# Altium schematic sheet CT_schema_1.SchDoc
size 488 x 436 mm
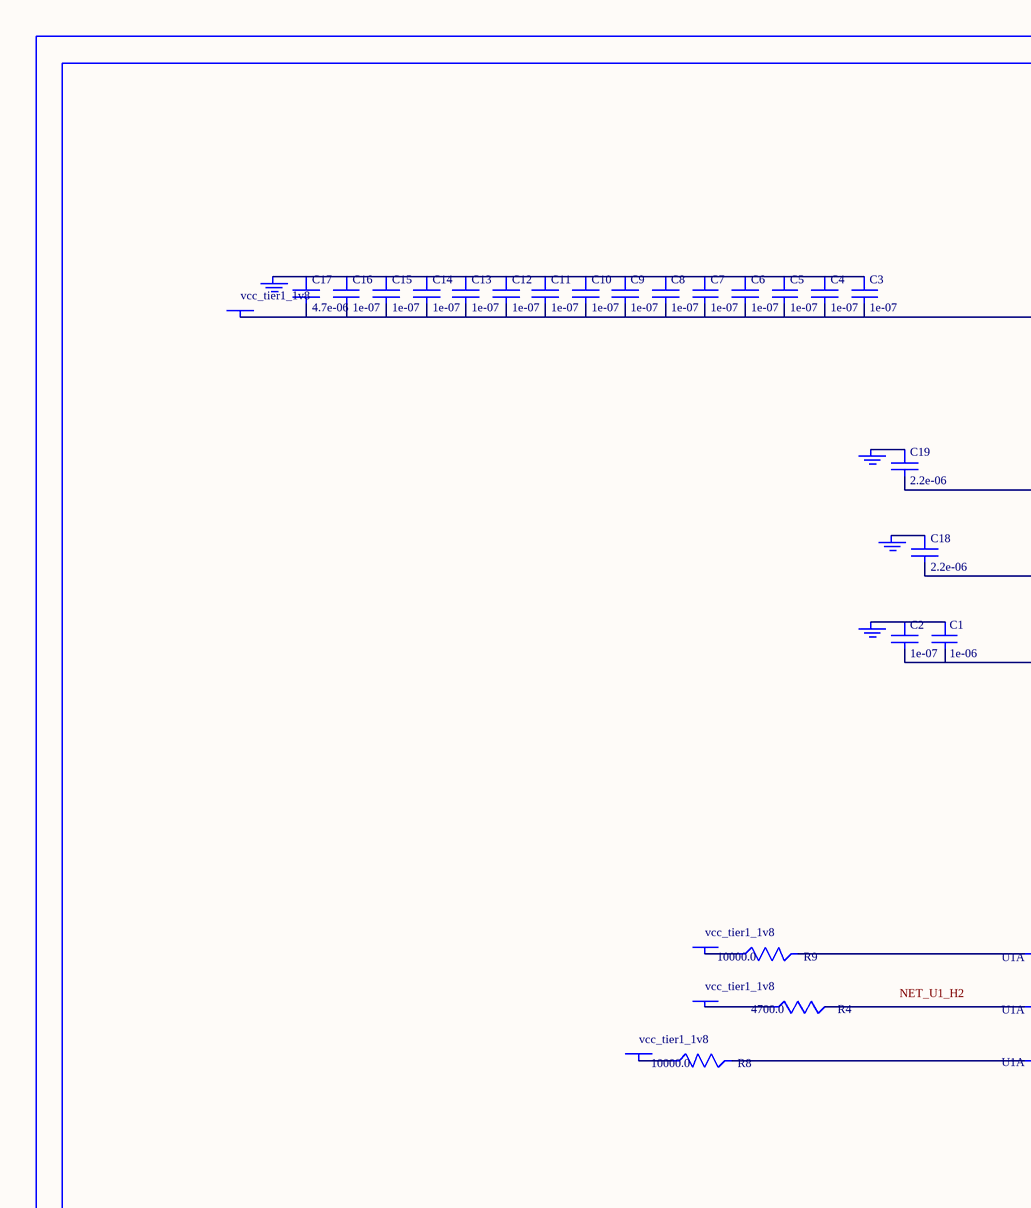
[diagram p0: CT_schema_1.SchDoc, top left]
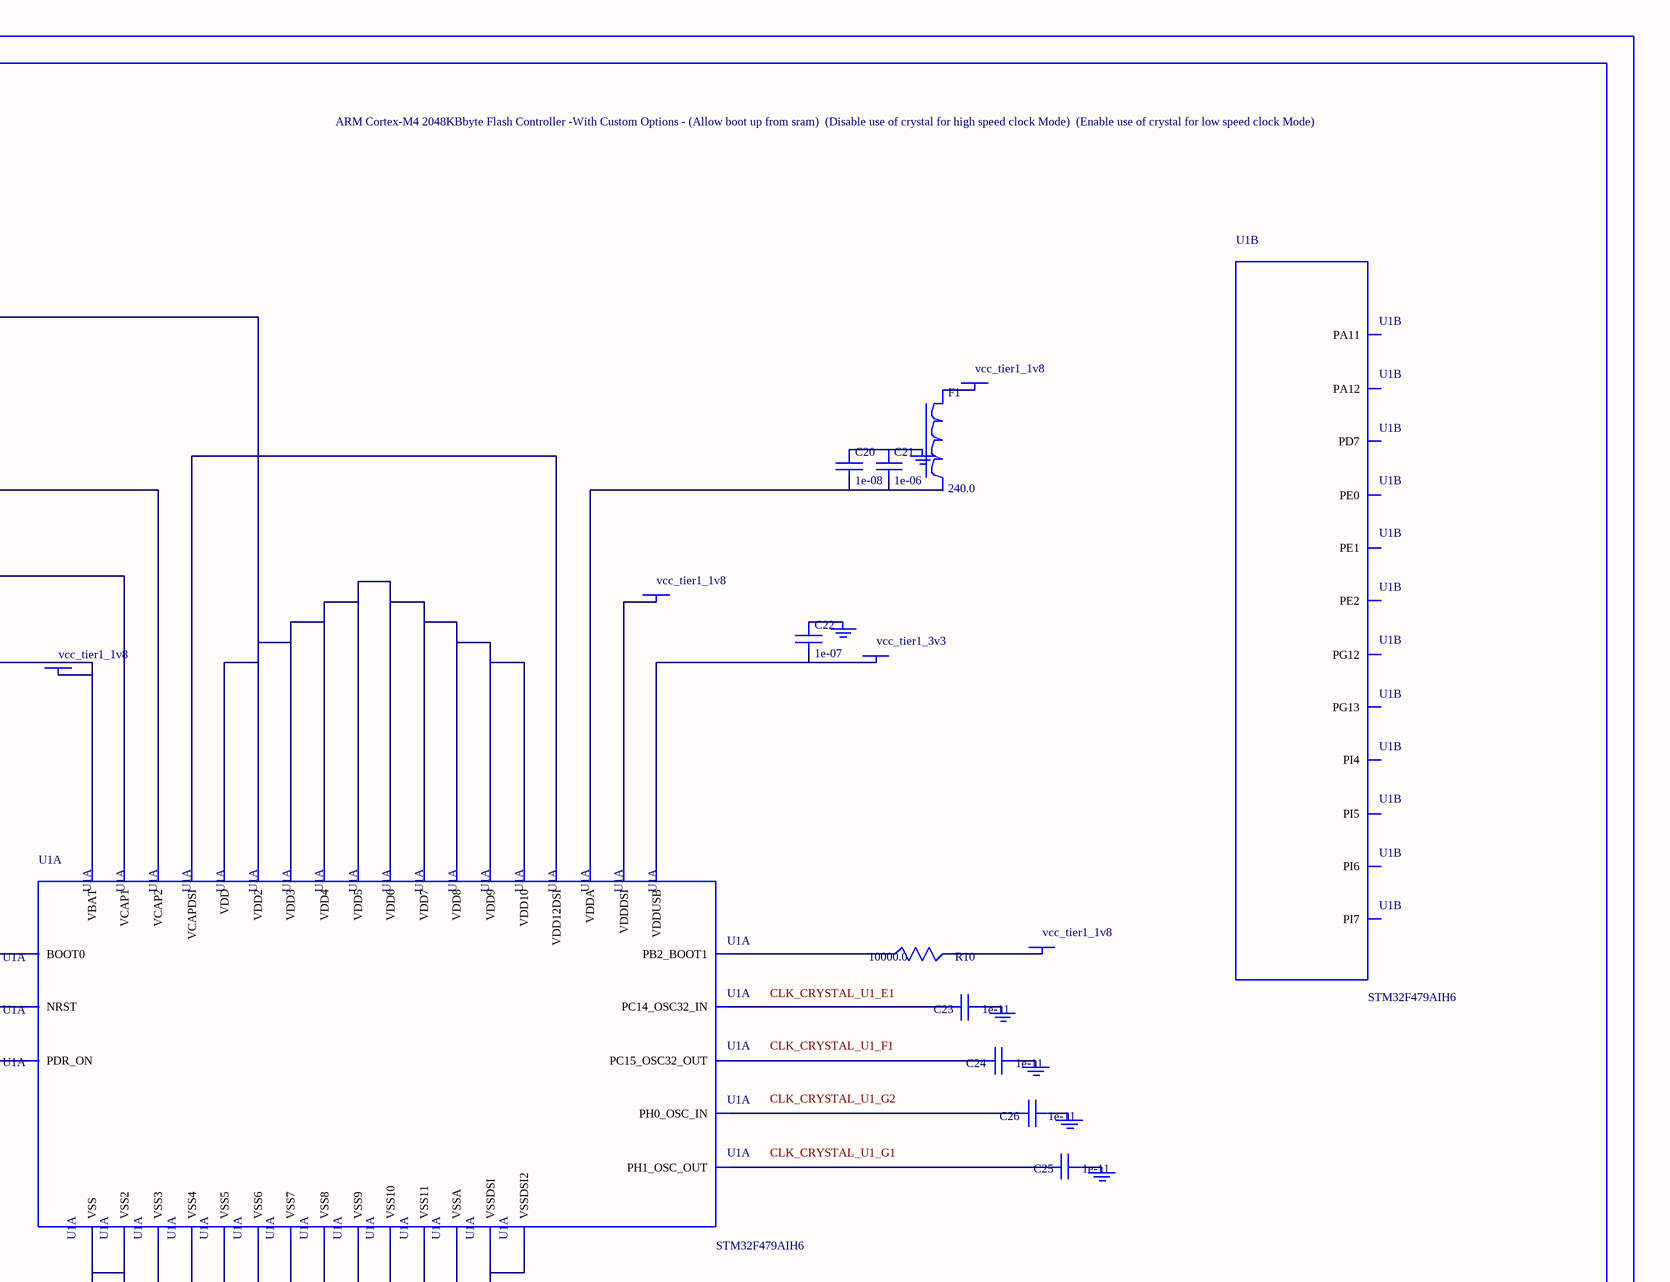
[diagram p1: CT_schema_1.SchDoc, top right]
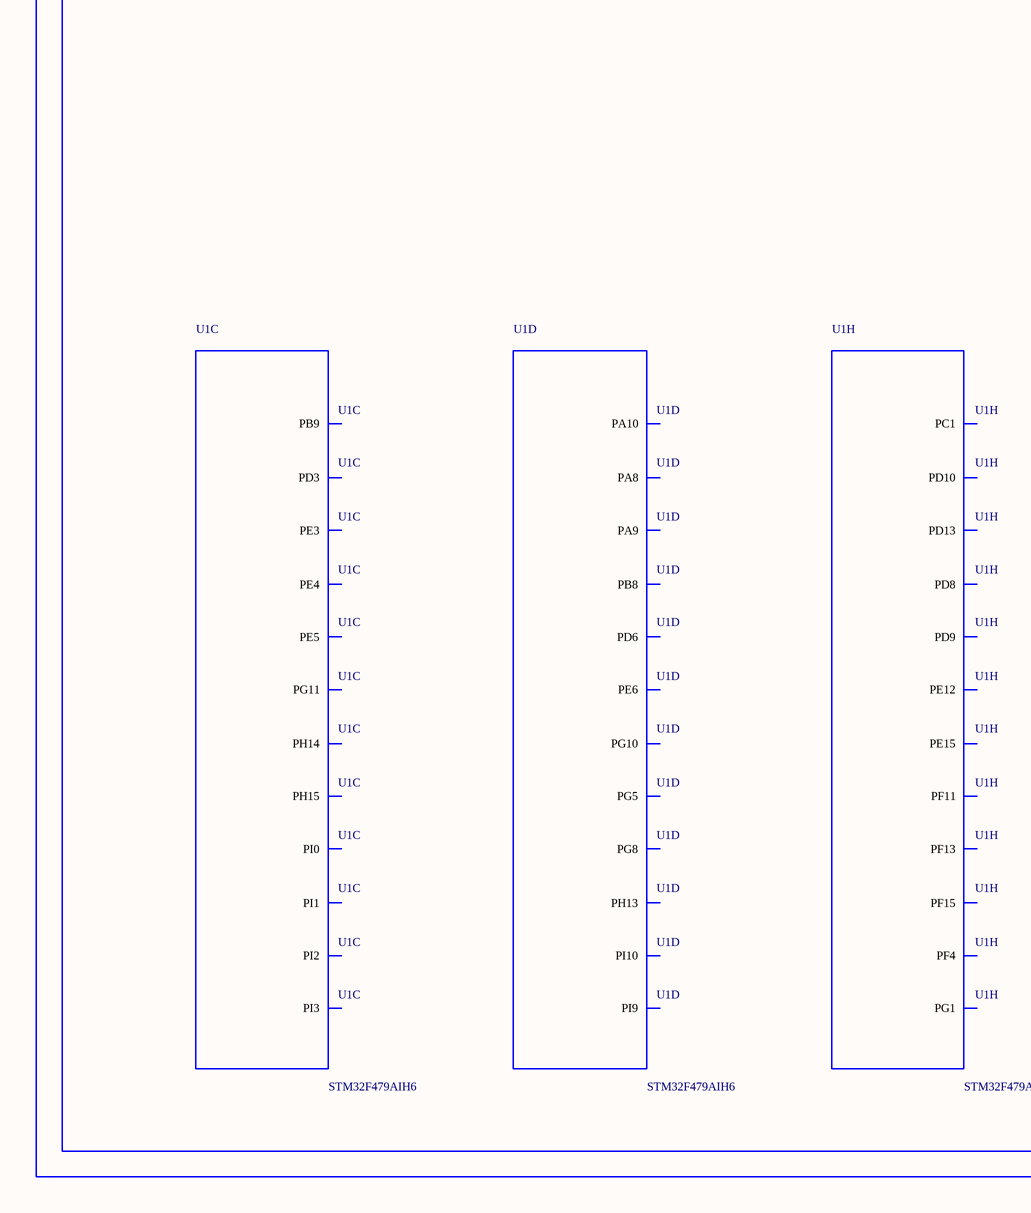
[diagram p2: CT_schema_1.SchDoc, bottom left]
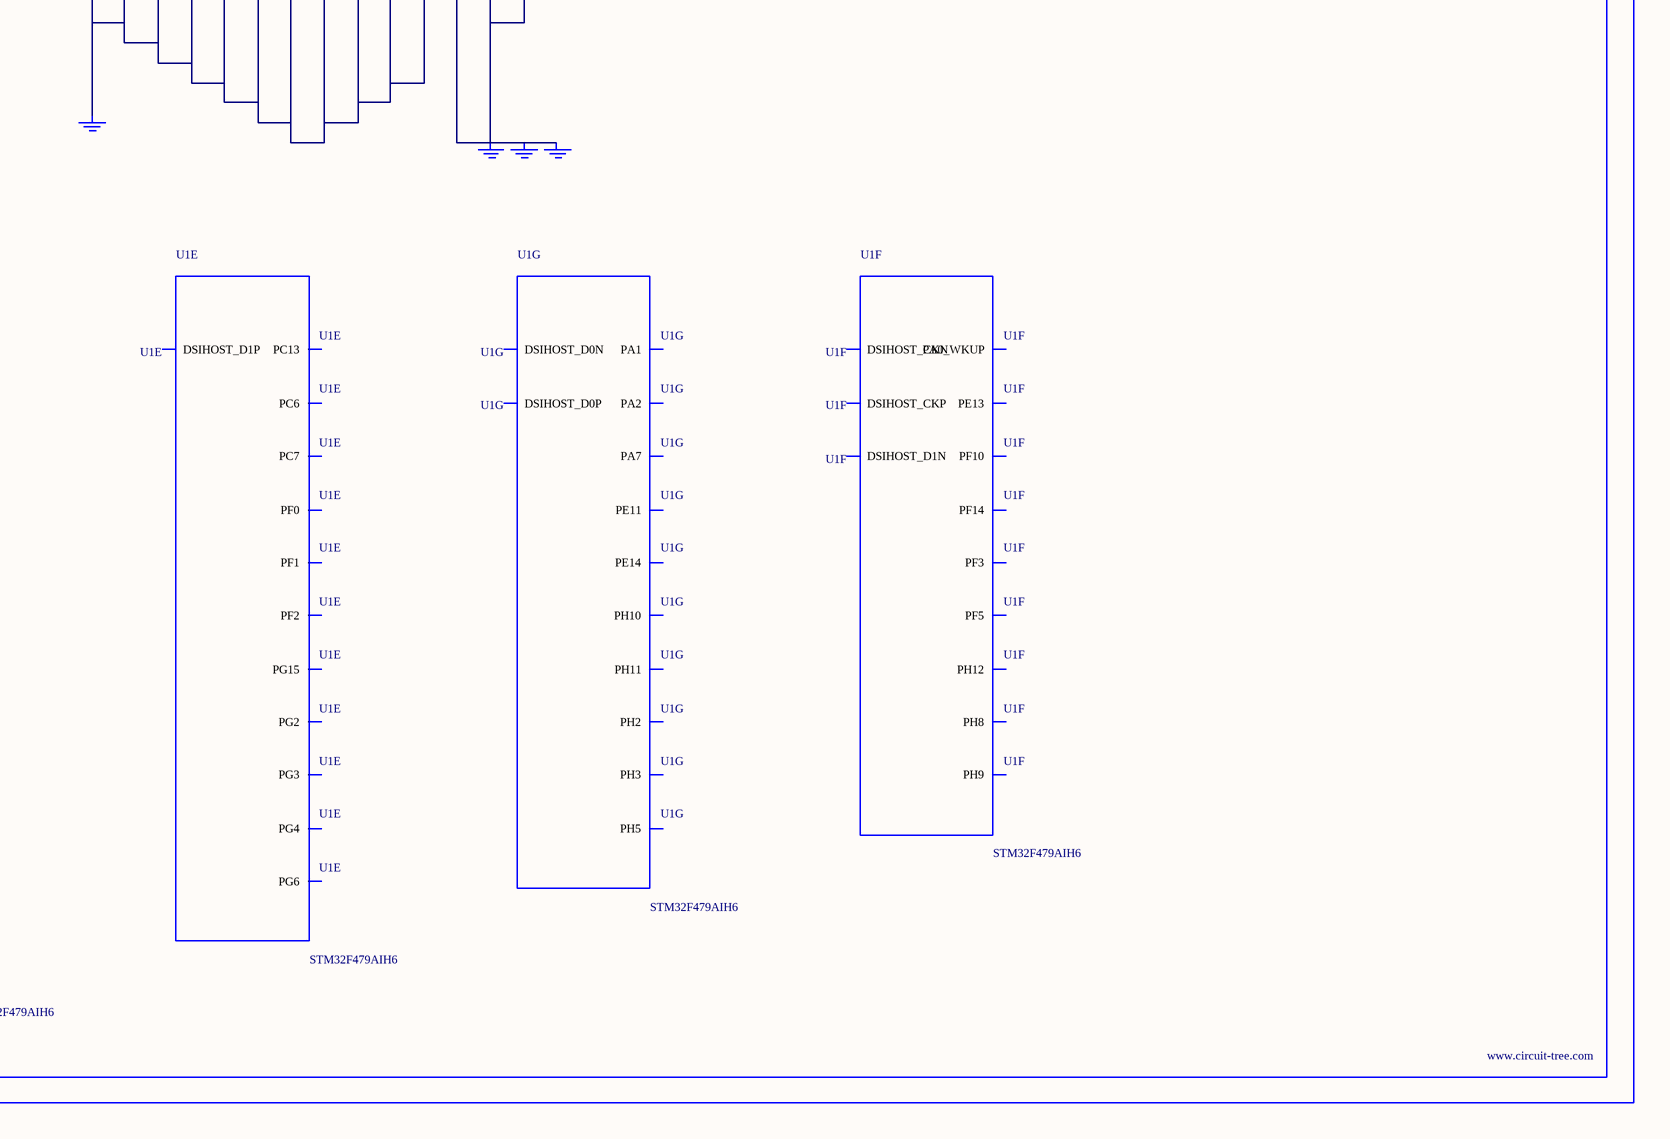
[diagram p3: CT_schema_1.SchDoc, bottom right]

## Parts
BORDER0  (no value)
C1  1e-06  [C0603]
C2  1e-07  [C0603]
C3  1e-07  [C0603]
C4  1e-07  [C0603]
C5  1e-07  [C0603]
C6  1e-07  [C0603]
C7  1e-07  [C0603]
C8  1e-07  [C0603]
C9  1e-07  [C0603]
C10  1e-07  [C0603]
C11  1e-07  [C0603]
C12  1e-07  [C0603]
C13  1e-07  [C0603]
C14  1e-07  [C0603]
C15  1e-07  [C0603]
C16  1e-07  [C0603]
C17  4.7e-06  [C0603]
C18  2.2e-06  [C0603]
C19  2.2e-06  [C0603]
C20  1e-08  [C0603]
C21  1e-06  [C0603]
C22  1e-07  [C0603]
C23  1e-11  [C0402]
C24  1e-11  [C0402]
C25  1e-11  [C0402]
C26  1e-11  [C0402]
F1  240.0  [L0603]
GND_INSTANCE_0_0  (no value)
GND_INSTANCE_0_1  (no value)
GND_INSTANCE_0_2  (no value)
GND_INSTANCE_0_3  (no value)
GND_INSTANCE_0_4  (no value)
GND_INSTANCE_0_5  (no value)
GND_INSTANCE_0_6  (no value)
GND_INSTANCE_0_7  (no value)
GND_INSTANCE_0_8  (no value)
GND_INSTANCE_0_9  (no value)
GND_INSTANCE_0_10  (no value)
GND_INSTANCE_0_11  (no value)
GND_INSTANCE_0_12  (no value)
GND_INSTANCE_0_13  (no value)
POWER_INSTANCE_0_0  vcc_tier1_1v8
POWER_INSTANCE_0_1  vcc_tier1_1v8
POWER_INSTANCE_0_2  vcc_tier1_1v8
POWER_INSTANCE_0_3  vcc_tier1_1v8
POWER_INSTANCE_0_4  vcc_tier1_3v3
POWER_INSTANCE_0_5  vcc_tier1_1v8
POWER_INSTANCE_0_6  vcc_tier1_1v8
POWER_INSTANCE_0_7  vcc_tier1_1v8
POWER_INSTANCE_0_8  vcc_tier1_1v8
R4  4700.0  [R0603]
R8  10000.0  [R0603]
R9  10000.0  [R0603]
R10  10000.0  [R0603]
U1  STM32F479AIH6  [UFBGA169]  (parts A,B,C,D,E,F,G,H of 14)

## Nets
NetC1_1: C1.1 C2.1 GND_INSTANCE_0_0.0(GND)
NetC1_2: C1.2 C2.2 POWER_INSTANCE_0_0.0(PWR) U1.E5(VBAT)
NetC3_1: C3.1 C4.1 C5.1 C6.1 C7.1 C8.1 C9.1 C10.1 C11.1 C12.1 C13.1 C14.1 C15.1 C16.1 C17.1 GND_INSTANCE_0_2.0(GND)
NetC3_2: C3.2 C4.2 C5.2 C6.2 C7.2 C8.2 C9.2 C10.2 C11.2 C12.2 C13.2 C14.2 C15.2 C16.2 C17.2 POWER_INSTANCE_0_2.0(PWR) U1.D3(VDD2) U1.D10(VDD) U1.F4(VDD3) U1.F7(VDD4) U1.G8(VDD5) U1.J4(VDD6) U1.K6(VDD8) U1.K10(VDD7) U1.L6(VDD9) U1.L9(VDD10)
NetC18_1: C18.1 GND_INSTANCE_0_3.0(GND)
NetC18_2: C18.2 U1.N9(VCAP1)
NetC19_1: C19.1 GND_INSTANCE_0_4.0(GND)
NetC19_2: C19.2 U1.D12(VCAP2)
NetC20_1: C20.1 C21.1 GND_INSTANCE_0_1.0(GND)
NetC20_2: C20.2 C21.2 U1.J3(VDDA)
NetC22_1: C22.1 GND_INSTANCE_0_5.0(GND)
NetC22_2: C22.2 POWER_INSTANCE_0_4.0(PWR) U1.G11(VDDUSB)
NetC23_1: C23.1 GND_INSTANCE_0_6.0(GND)
NetC23_2: C23.2 U1.E1(PC14_OSC32_IN)
NetC24_1: C24.1 GND_INSTANCE_0_7.0(GND)
NetC24_2: C24.2 U1.F1(PC15_OSC32_OUT)
NetC25_1: C25.1 GND_INSTANCE_0_8.0(GND)
NetC25_2: C25.2 U1.G1(PH1_OSC_OUT)
NetC26_1: C26.1 GND_INSTANCE_0_9.0(GND)
NetC26_2: C26.2 U1.G2(PH0_OSC_IN)
NetF1_1: F1.1 POWER_INSTANCE_0_1.0(PWR)
NetGND_INSTANCE_0_10_0: GND_INSTANCE_0_10.0(GND) GND_INSTANCE_0_11.0(GND) GND_INSTANCE_0_12.0(GND) U1.H11(VSSDSI) U1.J2(VSSA) U1.K11(VSSDSI2)
NetGND_INSTANCE_0_13_0: GND_INSTANCE_0_13.0(GND) U1.D11(VSS) U1.E3(VSS2) U1.F5(VSS3) U1.F8(VSS4) U1.G7(VSS5) U1.G9(VSS6) U1.J1(VSS7) U1.J6(VSS9) U1.J7(VSS10) U1.J10(VSS8) U1.M9(VSS11)
NetPOWER_INSTANCE_0_3_0: POWER_INSTANCE_0_3.0(PWR) R8.1
NetPOWER_INSTANCE_0_5_0: POWER_INSTANCE_0_5.0(PWR) R9.1
NetPOWER_INSTANCE_0_6_0: POWER_INSTANCE_0_6.0(PWR) R10.2
NetPOWER_INSTANCE_0_7_0: POWER_INSTANCE_0_7.0(PWR) U1.K13(VDDDSI)
NetPOWER_INSTANCE_0_8_0: POWER_INSTANCE_0_8.0(PWR) R4.1
NetR4_2: R4.2 U1.H2(NRST)
NetR8_2: R8.2 U1.C3(PDR_ON)
NetR9_2: R9.2 U1.A5(BOOT0)
NetR10_1: R10.1 U1.L5(PB2_BOOT1)
NetU1_J11: U1.J11(VDD12DSI) U1.K12(VCAPDSI)

Not connected (* = marked no-connect by the designer): F1 2; U1 A1(PI6) A2(PI5) A3(PE1) A4(PE0) A6(PG13) A7(PG12) A8(PD7) A12(PA12) A13(PA11) B1(PI7) B2(PE2) B3(PI4) B6(PG11) B10(PI3) B12(PI2) B13(PI0) C1(PE3) C2(PE4) C4(PB9) C8(PD3) C11(PI1) C12(PH15) C13(PH14) D1(PE5) D2(PE6) D4(PB8) D7(PD6) D8(PA8) D9(PH13) D13(PG8) E2(PI9) E4(PI10) E7(PG10) E8(PA9) E9(PA10) E12(PG5) E13(PG4) F3(PF0) F6(PG15) F9(PC6) F10(PC7) F11(PG6) F12(PG3) F13(PG2) G3(PF1) G4(PC13) G5(PF2) G12(DSIHOST_D1P) G13(DSIHOST_D1N) H1(PF10) H3(PF5) H4(PF3) H5(PF14) H8(PH8) H9(PH9) H10(PH12) H12(DSIHOST_CKP) H13(DSIHOST_CKN) J5(PA0_WKUP) J8(PE13) J9(PH10) J12(DSIHOST_D0P) J13(DSIHOST_D0N) K1(PA1) K2(PA2) K4(PA7) K7(PE11) K8(PE14) K9(PH11) L1(PH3) L2(PH2) L3(PH5) L4(PF4) L7(PE12) L8(PE15) L10(PD8) L11(PD10) M4(PF13) M5(PF11) M6(PF15) M7(PG1) M10(PD9) M12(PD13) N1(PC1)

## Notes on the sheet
- Labels drawn without touching a wire or pin: CLK_CRYSTAL_U1_E1, CLK_CRYSTAL_U1_F1, CLK_CRYSTAL_U1_G1, CLK_CRYSTAL_U1_G2, NET_U1_H2

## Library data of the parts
BORDER0 = BORDER_PAGE0
C1 C21 = C0603C105K3RACTU
C2-C16 C22 = 06035C104K4Z2A
C17 = GRM188R6YA475KE15D
C18 C19 = C0603C225K8RACTU
C20 = 06035C103K4Z2A
C23-C26 = C0402C100K3GACTU
F1 = Z0603C241ASMST
GND_INSTANCE_0_0-GND_INSTANCE_0_13 = GND
POWER_INSTANCE_0_0-POWER_INSTANCE_0_8 = PWR
R4 = RC0603JR-074K7L
R8-R10 = RC0603JR-0710KL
